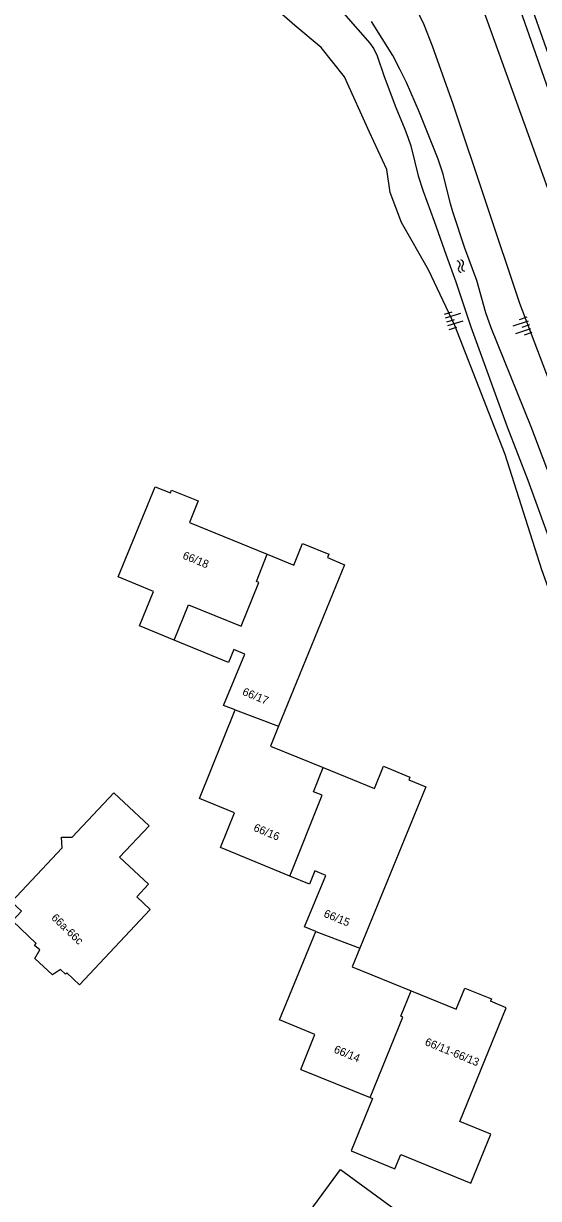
# Model space of a CAD drawing. Extents: x 135990 to 139000, y 393500 to 396000.
# Drawn here: x 136176.2 to 136240.4, y 395403.6 to 395550.4 of the extents above; entities that cross this region are included whole.
import ezdxf

# ---------------------------------------------------------------- set-up
doc = ezdxf.new("R2010")
doc.units = 0
for name, color, linetype in [('gg-anno-huisnummerreeks BGT', 7, 'Continuous'), ('gg-bbg-gedigitaliseerde bebouwing', 7, 'Continuous'), ('gg-bbg-gedigitaliseerde bijgebouw', 7, 'Continuous'), ('gg-bbg-hoofdgebouw', 7, 'Continuous'), ('gg-bbg-tussenscheiding', 7, 'Continuous'), ('gg-knt-verharding', 7, 'Continuous'), ('gt-symb-talud symbool', 7, 'Continuous'), ('gt-symb-watersymbool', 7, 'Continuous'), ('gx-grn-maaiveld', 7, 'Continuous')]:
    doc.layers.add(name, color=color, linetype=linetype)

# ---------------------------------------------------------------- blocks, each defined once
blk = doc.blocks.new('gt0-TALUD_1')
at = {"layer": 'gt-symb-talud symbool'}
for p, q in [((-1, -1), (-1, 0)), ((-0.5, -2), (-0.5, 0)), ((0, -1), (0, 0)), ((0.5, -2), (0.5, 0)), ((1, -1), (1, 0))]:
    blk.add_line(p, q, dxfattribs=at)
blk = doc.blocks.new('gt0-WA')
at = {"layer": 'gt-symb-watersymbool'}
for centre, start, end in [((-0.32, 0.02), 28.0725, 151.9275), ((0.43, 0.42), 208.0725, 331.9275), ((-0.32, -0.43), 28.0725, 151.9275), ((0.43, -0.03), 208.0725, 331.9275)]:
    blk.add_arc(centre, 0.425, start, end, dxfattribs=at)

msp = doc.modelspace()

# ---------------------------------------------------------------- linework, layer by layer
at = {"layer": 'gg-bbg-gedigitaliseerde bebouwing'}
for points in [[(136187.951, 395481.23), (136192.57, 395492.505), (136194.486, 395491.722), (136194.631, 395492.077), (136197.959, 395490.717), (136196.859, 395488.024), (136206.566, 395484.058)], [(136206.566, 395484.058), (136209.871, 395482.708), (136210.97, 395485.399), (136214.236, 395484.065), (136214.062, 395483.637), (136216.211, 395482.759), (136207.961, 395462.564)], [(136207.961, 395462.564), (136206.956, 395460.104), (136213.555, 395457.408)], [(136213.555, 395457.408), (136219.927, 395454.805), (136221.058, 395457.574), (136224.366, 395456.222), (136224.223, 395455.872), (136226.352, 395455.003), (136218.119, 395434.851)], [(136218.119, 395434.851), (136217.168, 395432.523), (136224.53, 395429.516)], [(136224.53, 395429.516), (136230.155, 395427.218), (136231.236, 395429.862), (136234.538, 395428.513), (136234.417, 395428.218)]]:
    msp.add_lwpolyline(points, dxfattribs=at)
at = {"layer": 'gg-bbg-gedigitaliseerde bijgebouw'}
msp.add_lwpolyline([(136210.102, 395399.55), (136215.699, 395407.194), (136224.082, 395401.079), (136218.448, 395393.465), (136210.102, 395399.55)], dxfattribs=at)
at = {"layer": 'gg-bbg-hoofdgebouw'}
msp.add_line((136210.761, 395419.71), (136219.388, 395416.182), dxfattribs=at)
for points in [[(136194.97, 395473.316), (136190.611, 395475.1), (136192.381, 395479.42), (136187.951, 395481.23)], [(136202.571, 395464.61), (136201.101, 395465.17), (136203.751, 395471.6), (136202.381, 395472.17), (136201.731, 395470.55), (136194.97, 395473.316)], [(136209.371, 395443.86), (136200.721, 395447.41), (136202.491, 395451.77), (136198.091, 395453.56), (136202.571, 395464.61)], [(136191.821, 395450.15), (136188.131, 395446.22), (136191.731, 395442.85), (136190.271, 395441.25), (136191.941, 395439.68), (136183.121, 395430.28), (136181.541, 395431.76), (136181.401, 395431.6), (136180.781, 395432.18), (136179.781, 395431.53), (136177.561, 395433.56), (136178.171, 395434.63), (136177.521, 395435.2), (136177.751, 395435.45), (136174.771, 395438.26), (136175.911, 395439.48), (136174.661, 395440.65), (136180.981, 395447.39), (136180.901, 395448.71), (136182.231, 395448.72), (136187.441, 395454.25), (136191.821, 395450.15)], [(136212.621, 395436.92), (136211.191, 395437.51), (136213.861, 395443.93), (136212.501, 395444.49), (136211.831, 395442.85), (136209.371, 395443.86)], [(136210.761, 395419.71), (136212.521, 395424.06), (136208.111, 395425.88), (136212.621, 395436.92)], [(136219.388, 395416.182), (136219.693, 395416.057), (136217.016, 395409.513), (136222.486, 395407.276), (136223.213, 395409.053), (136231.96, 395405.475), (136234.474, 395411.621), (136230.586, 395413.211), (136236.393, 395427.409), (136234.417, 395428.218)]]:
    msp.add_lwpolyline(points, dxfattribs=at)
at = {"layer": 'gg-bbg-tussenscheiding'}
for p, q in [((136202.571, 395464.61), (136207.961, 395462.564)), ((136212.621, 395436.92), (136218.119, 395434.851))]:
    msp.add_line(p, q, dxfattribs=at)
for points in [[(136194.97, 395473.316), (136196.74, 395477.723), (136203.318, 395475.08), (136205.516, 395480.554), (136205.208, 395480.678), (136206.566, 395484.058)], [(136209.371, 395443.86), (136213.415, 395453.947), (136212.34, 395454.379), (136213.555, 395457.408)], [(136219.388, 395416.182), (136223.477, 395426.236), (136223.236, 395426.334), (136224.53, 395429.516)]]:
    msp.add_lwpolyline(points, dxfattribs=at)
at = {"layer": 'gg-knt-verharding'}
msp.add_lwpolyline([(136157.159, 395790.858), (136168.331, 395760.2), (136176.251, 395725.65), (136212.461, 395622.74), (136229.361, 395577.101), (136254.981, 395504.101), (136255.48, 395500)], dxfattribs=at)
at = {"layer": 'gx-grn-maaiveld'}
for points in [[(136252.31, 395500), (136215.609, 395601.865), (136172.424, 395719.514), (136169.925, 395727.348), (136165.986, 395746.754)], [(136255.636, 395507.955), (136251.323, 395519.054), (136247.274, 395530.606), (136241.138, 395547.897), (136235.234, 395564.649), (136228.965, 395582.224), (136225.124, 395594.338), (136224.794, 395596.846), (136223.129, 395600.789), (136221.736, 395602.037), (136218.554, 395609.536), (136215.013, 395618.49), (136210.831, 395631.293), (136205.958, 395644.196), (136201.412, 395657.115), (136196.416, 395671.802)], [(136190.897, 395584.584), (136190.937, 395584.26), (136191.394, 395583.3), (136195.045, 395580.243), (136199.962, 395575.992), (136213.858, 395565.103), (136218.652, 395560.964), (136221.928, 395557.524), (136224.529, 395553.561), (136226.083, 395550.242), (136227.156, 395547.569), (136229.727, 395540.355), (136238.057, 395515.441), (136250.482, 395482.708), (136265.547, 395444.086), (136269.179, 395432.872), (136275.497, 395420.05), (136279.918, 395406.148), (136283.146, 395394.967), (136285.104, 395388.821), (136285.551, 395387.696), (136285.829, 395385.747)], [(136265.39, 395417.73), (136260.09, 395429.62), (136255.229, 395443.05), (136251.504, 395451.993), (136245.316, 395469.539), (136240.825, 395482.135), (136236.237, 395496.52), (136229.973, 395512.658), (136226.7, 395519.607), (136223.295, 395525.507), (136221.89, 395529.26), (136221.498, 395532.129), (136219.338, 395536.804), (136216.201, 395543.712), (136213.296, 395547.368), (136209.988, 395550.125), (136202.798, 395556.447), (136189.045, 395570.907), (136183.768, 395579.431)], [(136216.07, 395551.68), (136219.377, 395547.916), (136219.857, 395547.211), (136220.281, 395546.315), (136221.14, 395543.746), (136222.601, 395539.865), (136223.735, 395537.175), (136224.165, 395536.049), (136224.464, 395535.097), (136225.41, 395531.341), (136226.009, 395529.419), (136227.401, 395525.674), (136228.887, 395521.416), (136230.103, 395518.097), (136231.967, 395512.486), (136236.487, 395500), (136239.068, 395493.338), (136252.066, 395457.549), (136262.958, 395427.353), (136278.098, 395387.396)], [(136277.288, 395399.593), (136264.908, 395432.991), (136253.534, 395462.831), (136239.505, 395500), (136234.497, 395512.35), (136233.852, 395514.243), (136232.725, 395518.255), (136231.219, 395522.314), (136229.72, 395526.846), (136229.424, 395527.859), (136228.506, 395531.543), (136227.899, 395533.442), (136225.553, 395539.237), (136223.924, 395542.993), (136223.157, 395544.599), (136222.215, 395546.363), (136219.565, 395550.629)]]:
    msp.add_lwpolyline(points, dxfattribs=at)

# ---------------------------------------------------------------- block references
at = {"layer": 'gt-symb-talud symbool'}
for p, xscale, yscale, rotation in [((136228.922, 395513.066), 0.9998924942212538, 0.9998924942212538, 107.0395351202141), ((136239.307, 395512.758), 1.0002324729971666, 1.000232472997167, -71.4020222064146)]:
    msp.add_blockref('gt0-TALUD_1', p, dxfattribs=dict(at, xscale=xscale, yscale=yscale, rotation=rotation))
at = {"layer": 'gt-symb-watersymbool', "rotation": -71.03974891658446}
msp.add_blockref('gt0-WA', (136230.714, 395520.12), dxfattribs=at)

# ---------------------------------------------------------------- texts
at = {"layer": 'gg-anno-huisnummerreeks BGT'}
for s, rotation, p in [('66/18', 337.8, (136195.919, 395483.546)), ('66/17', 337.8, (136203.369, 395466.52)), ('66/16', 337.7, (136204.763, 395449.534)), ('66a-66c', 316.3, (136179.54, 395438.545)), ('66/15', 337.8, (136213.524, 395438.8)), ('66/14', 337.7, (136214.788, 395421.846)), ('66/11-66/13', 337.8, (136226.146, 395422.77))]:
    msp.add_text(s, height=1, rotation=rotation, dxfattribs=at).set_placement(p)

doc.saveas('drawing.dxf')
